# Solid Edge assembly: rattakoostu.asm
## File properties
Author: Türk
Template: Iso Assembly.asm
Last saved by: Türk
Revision: 10
Application: Solid Edge
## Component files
Rehv.par
VlegR18.par
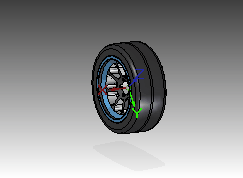
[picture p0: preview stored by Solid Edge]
